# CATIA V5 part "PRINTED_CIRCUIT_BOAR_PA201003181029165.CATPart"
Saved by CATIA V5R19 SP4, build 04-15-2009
Part number: PRINTED_CIRCUIT_BOAR_PA201003181029165
Bounding box of the stored display mesh (mm): x -15 to 15, y -2.5 to 2.5, z -1 to 0
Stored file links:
  E:\CadInnWork\1\PRINTED_CIRCUIT_BOAR_PA201003181029165.CATPart
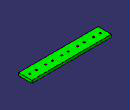
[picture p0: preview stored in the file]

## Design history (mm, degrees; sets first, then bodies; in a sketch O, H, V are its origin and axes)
Parameters
  Update = false
  PDM_version = "A"
  PDM_iteration = 1
  PDM_owner = "moren                    "
  PDM_comment = ""
  PDM_partnumber = "PA002170EA6A57201003181029160005"
Body1 (main body)
  Sketch1 on xy-plane, origin (0, 0, 0), H (1, 0, 0), V (0, 1, 0)
    line L1 (15, 2.5) -> (15, -2.5)
    line L2 (15, -2.5) -> (0, -2.5)
    line L3 (0, -2.5) -> (0, 2.5)
    line L4 (0, 2.5) -> (15, 2.5)
    reference intersected line E1 through (0, 0) direction (0, 1) from yz-plane
    length L4 = 15
    distance L2 L4 = 5
    vertical: L1 V, L3 V
    horizontal: L2 H, L4 H
    equidistance: L2 L4 O
    coincidence: L3 E1
  Pad1: profile Sketch1, direction (0, 0, -1), length 1
  Sketch2 on start face of Pad1, origin (0, 0, 0), H (1, 0, 0), V (0, 1, 0)
    line L1 (1.52, 0.25) -> (1.02, 0.25)
    line L2 (1.02, 0.25) -> (1.02, -0.25)
    line L3 (1.02, -0.25) -> (1.52, -0.25)
    line L4 (1.52, -0.25) -> (1.52, 0.25)
    reference intersected line E1 through (0, 0) direction (-1, 0) from zx-plane
    construction line L5 (1.27, 4.773) -> (1.27, -6.8318)
    reference intersected line E2 through (0, 0) direction (0, 1) from yz-plane
    distance L5 E2 = 1.27
    length L3 = 0.5
    length L2 = 0.5
    horizontal: L1 H, L3 H
    vertical: L2 V, L4 V, L5 V
    symmetry: L3 L1 E1, L2 L4 L5
  Pocket1: profile Sketch2, direction (0, 0, -1), through (limit type 3)
  Plane1: type Offset, RefPlane yz-plane, Offset 6
  Sketch3 on start face of Pad1, origin (0, 0, 0), H (1, 0, 0), V (0, 1, 0)
    line L1 (4.98, 0.25) -> (4.48, 0.25)
    line L2 (4.48, 0.25) -> (4.48, -0.25)
    line L3 (4.48, -0.25) -> (4.98, -0.25)
    line L4 (4.98, -0.25) -> (4.98, 0.25)
    construction line L5 (4.73, 1.2678) -> (4.73, -1.7139)
    reference intersected line E1 through (6, 0) direction (0, 1) from Plane1
    reference intersected line E2 through (0, 0) direction (-1, 0) from zx-plane
    distance E1 L5 = 1.27
    distance L4 L2 = 0.5
    length L2 = 0.5
    horizontal: L1 H, L3 H
    vertical: L2 V, L4 V, L5 V
    symmetry: L2 L4 L5, L3 L1 E2
  Pocket2: profile Sketch3, direction (0, 0, -1), through (limit type 3)
  Mirror1: of Pocket2, about Plane1
  RectPattern1: of Pocket2, direction 1 instances 2, spacing 6, along edge [face of Pad1 from Sketch1.L2 | start face of Pad1]
  Plane2: type Offset, RefPlane Plane1, Offset 6
  Sketch4 on start face of Pad1, origin (0, 0, 0), H (1, 0, 0), V (0, 1, 0)
    line L1 (13.02, 0.25) -> (13.52, 0.25)
    line L2 (13.52, 0.25) -> (13.52, -0.25)
    line L3 (13.52, -0.25) -> (13.02, -0.25)
    line L4 (13.02, -0.25) -> (13.02, 0.25)
    reference projected line E1 (10.98, -0.25) -> (10.98, 0.25) from edge [start face of Pad1 | face of RectPattern1]
    reference intersected line E2 through (12, 0) direction (0, 1) from Plane2
    reference intersected line E3 through (0, 0) direction (-1, 0) from zx-plane
    length L3 = 0.5
    length L2 = 0.5
    horizontal: L1 H, L3 H
    vertical: L2 V, L4 V
    symmetry: L4 E1 E2, L3 L1 E3
  Pocket3: profile Sketch4, direction (0, 0, -1), through (limit type 3)
  Mirror2: of the body so far, about yz-plane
